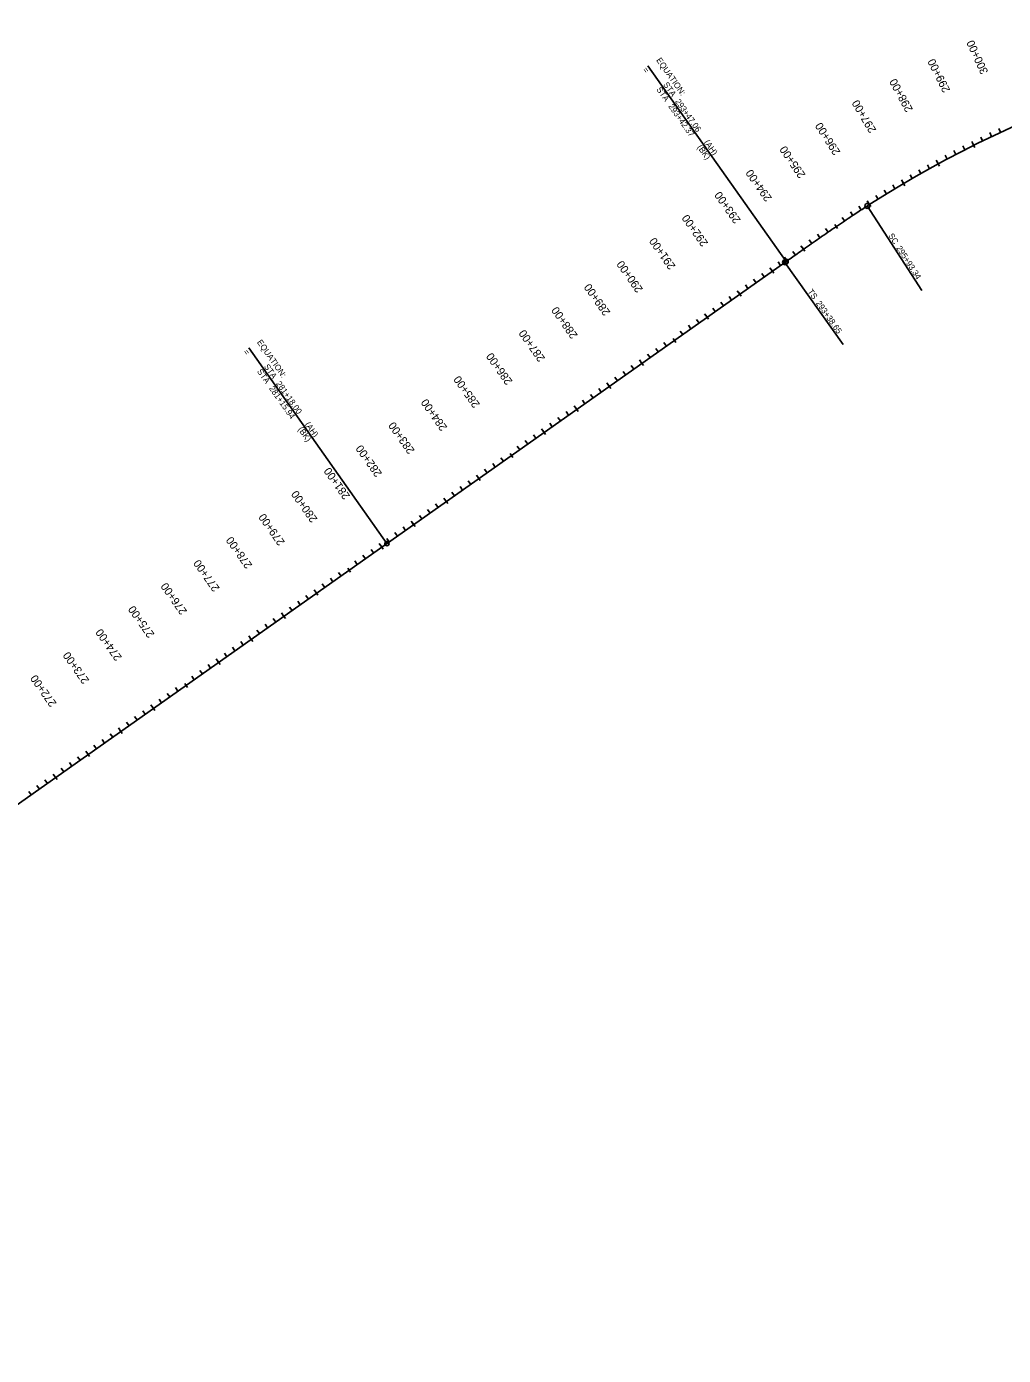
# Model space of a CAD drawing. Extents: x 22693007 to 22771804, y 6223023 to 6251673.
# Drawn here: x 22705317 to 22707763, y 6232173 to 6235501 of the extents above; entities that cross this region are included whole.
import ezdxf

# ---------------------------------------------------------------- set-up
doc = ezdxf.new("R2010")
doc.units = 0
for name, color, linetype in [('Default', 7, 'Continuous'), ('Draft_2', 7, 'Continuous'), ('NamedBoundary', 7, 'Continuous'), ('SheetBorder', 7, 'Continuous'), ('TextAlignment', 7, 'Continuous')]:
    doc.layers.add(name, color=color, linetype=linetype)

msp = doc.modelspace()

# ---------------------------------------------------------------- linework, layer by layer
at = {"layer": 'Default'}
msp.add_line((22703341, 6232172.5), (22707216.1, 6234910.4), dxfattribs=at)
msp.add_arc((22708971.9, 6232641.9), 2865, 93.6984, 122.7427, dxfattribs=at)
msp.add_open_spline([(22707216.1, 6234910.4), (22707224.6, 6234916.4), (22707241.6, 6234928.4), (22707275.7, 6234952.4), (22707318.4, 6234982.2), (22707361.4, 6235011.6), (22707396.1, 6235034.7), (22707413.6, 6235046), (22707422.3, 6235051.7)], degree=3, dxfattribs=at)
at = {"layer": 'Draft_2'}
for p, q in [((22707688.7, 6235203.4), (22707683.8, 6235213.2)), ((22707600, 6235157.1), (22707594.8, 6235166.7)), ((22707513.1, 6235107.7), (22707507.5, 6235117.1)), ((22707427.9, 6235055.3), (22707422.1, 6235064.5)), ((22707341.1, 6235005.1), (22707348, 6234995)), ((22707262.4, 6234943.1), (22707256.1, 6234952)), ((22707184.5, 6234888.1), (22707178.2, 6234897)), ((22707102.9, 6234830.4), (22707096.6, 6234839.3)), ((22707021.2, 6234772.7), (22707014.9, 6234781.6)), ((22706936, 6234720), (22706943.1, 6234710)), ((22706857.9, 6234657.3), (22706851.6, 6234666.2)), ((22706776.2, 6234599.6), (22706769.9, 6234608.5)), ((22706694.5, 6234541.9), (22706688.2, 6234550.8)), ((22706612.8, 6234484.2), (22706606.5, 6234493.1)), ((22706527.6, 6234431.5), (22706534.7, 6234421.5)), ((22706449.5, 6234368.8), (22706443.2, 6234377.7)), ((22706367.8, 6234311.1), (22706361.5, 6234320)), ((22706286.2, 6234253.4), (22706279.8, 6234262.3)), ((22706206.2, 6234196.8), (22706199.9, 6234205.8)), ((22706121, 6234144.1), (22706128, 6234134.1)), ((22706042.8, 6234081.4), (22706036.5, 6234090.3)), ((22705961.1, 6234023.7), (22705954.8, 6234032.6)), ((22705879.5, 6233966), (22705873.2, 6233974.9)), ((22705797.8, 6233908.3), (22705791.5, 6233917.2)), ((22705712.6, 6233855.6), (22705719.7, 6233845.6)), ((22705634.5, 6233792.9), (22705628.2, 6233801.8)), ((22705552.8, 6233735.2), (22705546.5, 6233744.1)), ((22705471.1, 6233677.5), (22705464.8, 6233686.4)), ((22705389.4, 6233619.8), (22705383.1, 6233628.7))]:
    msp.add_line(p, q, dxfattribs=at)
at = {"layer": 'NamedBoundary'}
msp.add_line((22703341, 6232172.5), (22707216.1, 6234910.4), dxfattribs=at)
msp.add_arc((22708971.9, 6232641.9), 2865, 93.6984, 122.7427, dxfattribs=at)
msp.add_open_spline([(22707216.1, 6234910.4), (22707224.6, 6234916.4), (22707241.6, 6234928.4), (22707275.7, 6234952.4), (22707318.4, 6234982.2), (22707361.4, 6235011.6), (22707396.1, 6235034.7), (22707413.6, 6235046), (22707422.3, 6235051.7)], degree=3, dxfattribs=at)
at = {"layer": 'SheetBorder'}
for p, q in [((22707711.1, 6235214.5), (22707706.2, 6235224.3)), ((22707733.6, 6235225.4), (22707728.8, 6235235.3)), ((22707756.1, 6235236.1), (22707751.5, 6235246)), ((22707644.1, 6235180.6), (22707639.1, 6235190.3)), ((22707666.4, 6235192.1), (22707661.4, 6235201.8)), ((22707685.9, 6235208.9), (22707691.4, 6235197.9)), ((22707578.2, 6235145), (22707572.8, 6235154.5)), ((22707597.1, 6235162.4), (22707603, 6235151.7)), ((22707622, 6235168.9), (22707616.9, 6235178.6)), ((22707534.7, 6235120.3), (22707529.2, 6235129.7)), ((22707556.4, 6235132.7), (22707551, 6235142.2)), ((22707470.3, 6235081.8), (22707464.6, 6235091.1)), ((22707491.6, 6235094.8), (22707486, 6235104.2)), ((22707510, 6235112.9), (22707516.2, 6235102.4)), ((22707424.7, 6235060.4), (22707431.2, 6235050.1)), ((22707449.1, 6235068.6), (22707443.3, 6235077.9)), ((22707365.3, 6235014.1), (22707359.2, 6235023.1)), ((22707386.1, 6235028), (22707380, 6235037.1)), ((22707406.9, 6235041.7), (22707401, 6235050.8)), ((22707323.9, 6234985.9), (22707317.7, 6234994.9)), ((22707341.1, 6235005.1), (22707348, 6234995)), ((22707282.9, 6234957.4), (22707276.6, 6234966.4)), ((22707303.4, 6234971.7), (22707297.1, 6234980.7)), ((22707221.5, 6234914.2), (22707215.2, 6234923.2)), ((22707242, 6234928.7), (22707235.7, 6234937.6)), ((22707258.9, 6234948.1), (22707265.9, 6234938.1)), ((22707181, 6234893.1), (22707188.1, 6234883.1)), ((22707205, 6234902.5), (22707198.7, 6234911.4)), ((22707143.7, 6234859.2), (22707137.4, 6234868.2)), ((22707164.1, 6234873.7), (22707157.8, 6234882.6)), ((22707082.4, 6234816), (22707076.1, 6234824.9)), ((22707099.3, 6234835.4), (22707106.4, 6234825.4)), ((22707123.3, 6234844.8), (22707117, 6234853.7)), ((22707041.6, 6234787.1), (22707035.3, 6234796)), ((22707062, 6234801.5), (22707055.7, 6234810.5)), ((22707000.8, 6234758.3), (22706994.5, 6234767.2)), ((22707017.7, 6234777.7), (22707024.7, 6234767.7)), ((22706959.9, 6234729.4), (22706953.6, 6234738.3)), ((22706980.4, 6234743.8), (22706974.1, 6234752.8)), ((22706898.7, 6234686.1), (22706892.4, 6234695)), ((22706919.1, 6234700.6), (22706912.8, 6234709.5)), ((22706936, 6234720), (22706943.1, 6234710)), ((22706854.3, 6234662.3), (22706861.4, 6234652.3)), ((22706878.3, 6234671.7), (22706872, 6234680.6)), ((22706796.6, 6234614), (22706790.3, 6234622.9)), ((22706817, 6234628.4), (22706810.7, 6234637.3)), ((22706837.4, 6234642.9), (22706831.1, 6234651.8)), ((22706755.8, 6234585.1), (22706749.5, 6234594.1)), ((22706772.6, 6234604.6), (22706779.7, 6234594.6)), ((22706714.9, 6234556.3), (22706708.6, 6234565.2)), ((22706735.3, 6234570.7), (22706729, 6234579.6)), ((22706653.7, 6234513), (22706647.4, 6234521.9)), ((22706674.1, 6234527.4), (22706667.8, 6234536.4)), ((22706691, 6234546.9), (22706698, 6234536.9)), ((22706609.3, 6234489.2), (22706616.4, 6234479.2)), ((22706633.3, 6234498.6), (22706627, 6234507.5)), ((22706572, 6234455.3), (22706565.7, 6234464.2)), ((22706592.4, 6234469.7), (22706586.1, 6234478.7)), ((22706527.6, 6234431.5), (22706534.7, 6234421.5)), ((22706551.6, 6234440.9), (22706545.3, 6234449.8)), ((22706469.9, 6234383.2), (22706463.6, 6234392.1)), ((22706490.3, 6234397.6), (22706484, 6234406.5)), ((22706510.7, 6234412), (22706504.4, 6234421)), ((22706429.1, 6234354.3), (22706422.8, 6234363.3)), ((22706446, 6234373.8), (22706453, 6234363.8)), ((22706388.2, 6234325.5), (22706381.9, 6234334.4)), ((22706408.7, 6234339.9), (22706402.4, 6234348.8)), ((22706327, 6234282.2), (22706320.7, 6234291.1)), ((22706347.4, 6234296.6), (22706341.1, 6234305.5)), ((22706364.3, 6234316.1), (22706371.4, 6234306.1)), ((22706282.6, 6234258.3), (22706289.7, 6234248.4)), ((22706306.6, 6234267.8), (22706300.3, 6234276.7)), ((22706245.3, 6234224.5), (22706239, 6234233.4)), ((22706265.7, 6234238.9), (22706259.4, 6234247.8)), ((22706185.7, 6234182.4), (22706179.4, 6234191.3)), ((22706202.6, 6234201.8), (22706209.7, 6234191.8)), ((22706224.9, 6234210.1), (22706218.6, 6234219)), ((22706144.9, 6234153.6), (22706138.6, 6234162.5)), ((22706165.3, 6234168), (22706159, 6234176.9)), ((22706104.1, 6234124.7), (22706097.8, 6234133.6)), ((22706121, 6234144.1), (22706128, 6234134.1)), ((22706063.2, 6234095.9), (22706056.9, 6234104.8)), ((22706083.7, 6234110.3), (22706077.4, 6234119.2)), ((22706002, 6234052.6), (22705995.7, 6234061.5)), ((22706022.4, 6234067), (22706016.1, 6234075.9)), ((22706039.3, 6234086.4), (22706046.3, 6234076.4)), ((22705957.6, 6234028.7), (22705964.7, 6234018.7)), ((22705981.6, 6234038.1), (22705975.3, 6234047.1)), ((22705899.9, 6233980.4), (22705893.6, 6233989.4)), ((22705920.3, 6233994.9), (22705914, 6234003.8)), ((22705940.7, 6234009.3), (22705934.4, 6234018.2)), ((22705859.1, 6233951.6), (22705852.8, 6233960.5)), ((22705875.9, 6233971), (22705883, 6233961)), ((22705818.2, 6233922.7), (22705811.9, 6233931.7)), ((22705838.6, 6233937.2), (22705832.3, 6233946.1)), ((22705777.4, 6233893.9), (22705771.1, 6233902.8)), ((22705794.3, 6233913.3), (22705801.3, 6233903.3)), ((22705736.5, 6233865), (22705730.2, 6233874)), ((22705757, 6233879.5), (22705750.7, 6233888.4)), ((22705675.3, 6233821.8), (22705669, 6233830.7)), ((22705695.7, 6233836.2), (22705689.4, 6233845.1)), ((22705712.6, 6233855.6), (22705719.7, 6233845.6)), ((22705630.9, 6233797.9), (22705638, 6233787.9)), ((22705654.9, 6233807.3), (22705648.6, 6233816.3)), ((22705573.2, 6233749.6), (22705566.9, 6233758.5)), ((22705593.6, 6233764.1), (22705587.3, 6233773)), ((22705614, 6233778.5), (22705607.7, 6233787.4)), ((22705532.4, 6233720.8), (22705526.1, 6233729.7)), ((22705549.3, 6233740.2), (22705556.3, 6233730.2)), ((22705491.5, 6233691.9), (22705485.2, 6233700.8)), ((22705512, 6233706.4), (22705505.7, 6233715.3)), ((22705430.3, 6233648.6), (22705424, 6233657.6)), ((22705450.7, 6233663.1), (22705444.4, 6233672)), ((22705467.6, 6233682.5), (22705474.6, 6233672.5)), ((22705385.9, 6233624.8), (22705393, 6233614.8)), ((22705409.9, 6233634.2), (22705403.6, 6233643.1)), ((22705348.6, 6233590.9), (22705342.3, 6233599.9)), ((22705369, 6233605.4), (22705362.7, 6233614.3)), ((22705328.2, 6233576.5), (22705321.9, 6233585.4))]:
    msp.add_line(p, q, dxfattribs=at)
at = {"layer": 'TextAlignment'}
for p, q in [((22707219.1, 6234912.5), (22706872.9, 6235402.6)), ((22706872.9, 6235402.6), (22706872.9, 6235402.6)), ((22707422.3, 6235051.7), (22707558.6, 6234839.7)), ((22707422.3, 6235051.7), (22707558.6, 6234839.7)), ((22707216.1, 6234910.4), (22707361.5, 6234704.6)), ((22707558.6, 6234839.7), (22707558.6, 6234839.7)), ((22707558.6, 6234839.7), (22707558.6, 6234839.7)), ((22706219.2, 6234206), (22705873, 6234696.1)), ((22705873, 6234696.1), (22705873, 6234696.1)), ((22707361.5, 6234704.6), (22707361.5, 6234704.6))]:
    msp.add_line(p, q, dxfattribs=at)
for centre, radius in [((22707422.3, 6235051.7), 6.24), ((22707422.3, 6235051.7), 6.24), ((22707216.1, 6234910.4), 6.24), ((22707219.1, 6234912.5), 5.34), ((22706219.2, 6234206), 5.34)]:
    msp.add_circle(centre, radius, dxfattribs=at)

# ---------------------------------------------------------------- texts
at = {"layer": 'Draft_2'}
for s, rotation, p in [('300+00', 114.6101, (22707725.5, 6235387.2)), ('295+00', 124.2609, (22707268.4, 6235129.7)), ('290+00', 125.2425, (22706861.2, 6234843.3)), ('285+00', 125.2425, (22706452.8, 6234554.8)), ('280+00', 125.2425, (22706046.1, 6234267.4)), ('275+00', 125.2425, (22705637.8, 6233978.9))]:
    msp.add_text(s, height=20.04, rotation=rotation, dxfattribs=at).set_placement(p)
at = {"layer": 'SheetBorder'}
for s, rotation, p in [('300+00', 114.6101, (22707725.5, 6235387.2)), ('299+00', 116.61, (22707630.4, 6235342)), ('298+00', 118.6099, (22707537, 6235293.6)), ('297+00', 120.6097, (22707445.4, 6235241.9)), ('296+00', 122.6096, (22707355.6, 6235187)), ('295+00', 124.2609, (22707268.4, 6235129.7)), ('294+00', 125.1141, (22707184.3, 6235071.5)), ('293+00', 125.2425, (22707106.2, 6235016.4)), ('292+00', 125.2425, (22707024.5, 6234958.7)), ('291+00', 125.2425, (22706942.8, 6234901)), ('290+00', 125.2425, (22706861.2, 6234843.3)), ('289+00', 125.2425, (22706779.5, 6234785.6)), ('288+00', 125.2425, (22706697.8, 6234727.9)), ('287+00', 125.2425, (22706616.1, 6234670.2)), ('286+00', 125.2425, (22706534.5, 6234612.5)), ('285+00', 125.2425, (22706452.8, 6234554.8)), ('284+00', 125.2425, (22706371.1, 6234497)), ('283+00', 125.2425, (22706289.5, 6234439.3)), ('282+00', 125.2425, (22706207.8, 6234381.6)), ('281+00', 125.2425, (22706127.8, 6234325.1)), ('280+00', 125.2425, (22706046.1, 6234267.4)), ('279+00', 125.2425, (22705964.4, 6234209.7)), ('278+00', 125.2425, (22705882.8, 6234152)), ('277+00', 125.2425, (22705801.1, 6234094.3)), ('276+00', 125.2425, (22705719.4, 6234036.6)), ('275+00', 125.2425, (22705637.8, 6233978.9)), ('274+00', 125.2425, (22705556.1, 6233921.2)), ('273+00', 125.2425, (22705474.4, 6233863.5)), ('272+00', 125.2425, (22705392.7, 6233805.8))]:
    msp.add_text(s, height=20.04, rotation=rotation, dxfattribs=at).set_placement(p)
at = {"layer": 'TextAlignment'}
for s, rotation, p in [('EQUATION:', 305.242, (22706892.8, 6235416.6)), ('=', 305.242, (22706858.5, 6235392.4)), ('STA ', 305.242, (22706910.3, 6235355.5)), ('STA ', 305.242, (22706893.1, 6235343.4)), ('293+42.37', 305.242, (22706923.1, 6235300.9)), ('293+47.06', 305.242, (22706940.2, 6235313.1)), ('(BK)', 305.242, (22706995.4, 6235198.6)), ('(AH)', 305.242, (22707012.5, 6235210.7)), ('SC', 302.7427, (22707474.1, 6234977.3)), ('SC', 302.7427, (22707474.1, 6234977.3)), ('295+93.34', 302.7427, (22707494.1, 6234946.1)), ('295+93.34', 302.7427, (22707494.1, 6234946.1)), ('TS', 305.2425, (22707271.9, 6234837.1)), ('293+38.65', 305.2425, (22707292.7, 6234807.7)), ('=', 305.2425, (22705858.5, 6234685.9)), ('EQUATION:', 305.2425, (22705892.8, 6234710.1)), ('STA ', 305.2425, (22705910.3, 6234649)), ('STA ', 305.2425, (22705893.1, 6234636.9)), ('281+15.94', 305.2425, (22705923.1, 6234594.4)), ('281+18.00', 305.2425, (22705940.3, 6234606.5)), ('(BK)', 305.2425, (22705995.4, 6234492.1)), ('(AH)', 305.2425, (22706012.6, 6234504.2))]:
    msp.add_text(s, height=15, rotation=rotation, dxfattribs=at).set_placement(p)

doc.saveas('drawing.dxf')
